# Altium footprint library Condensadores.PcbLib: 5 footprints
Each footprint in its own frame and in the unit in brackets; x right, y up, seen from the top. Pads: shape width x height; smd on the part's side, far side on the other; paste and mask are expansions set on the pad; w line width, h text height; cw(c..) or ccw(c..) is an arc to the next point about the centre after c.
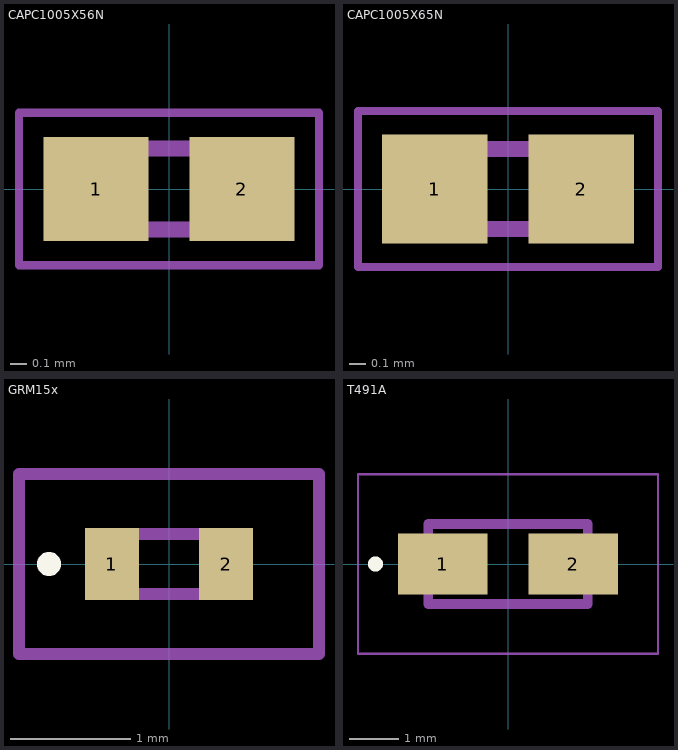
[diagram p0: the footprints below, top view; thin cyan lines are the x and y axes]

## CAPC1005X56N [mm]
pads (2):
  rect 0.65x0.64 smd: 1(-0.45,0) 2(0.45,0)
Mechanical 13:
  lines w0.1: -0.5,-0.25 0.5,-0.25 0.5,0.25 -0.5,0.25 -0.5,-0.25
Mechanical 15:
  lines w0.05: -0.925,-0.47 0.925,-0.47 0.925,0.47 -0.925,0.47 -0.925,-0.47
3D body "0402YC104KAT2A.stp": height 0.56, standoff 0, extent -0.5,-0.25 0.5,0.25

## CAPC1005X65N [mm]
pads (2):
  rect 0.66x0.68 smd: 1(-0.46,0) 2(0.46,0)
Mechanical 13:
  lines w0.1: -0.5,-0.25 -0.5,0.25 0.5,0.25 0.5,-0.25 -0.5,-0.25
Mechanical 15:
  lines w0.05: -0.94,-0.49 -0.94,0.49 0.94,0.49 0.94,-0.49 -0.94,-0.49
3D body "CL05A105KL5NRNC.stp": height 0.65, standoff 0, extent -0.5,-0.25 0.5,0.25

## GRM15x [mm]
pads (2):
  rect 0.45x0.6 smd: 1(-0.475,0) 2(0.475,0)
Top Overlay:
  lines w0.1: -1,-0.05 ccw(c-1,0) -1,0.05 ccw(c-1,0) -1,-0.05
Mechanical 13:
  lines w0.1: -0.5,-0.25 -0.5,0.25 0.5,0.25 0.5,-0.25 -0.5,-0.25
Mechanical 15:
  lines w0.1: -1.25,-0.75 -1.25,0.75 1.25,0.75 1.25,-0.75 -1.25,-0.75
3D body "GRM155R61A106ME11J.stp": height 0.5, standoff 0, extent -0.5,-0.28 0.5,0.27

## PCBComponent_1 [mm]

## T491A [mm]
pads (2):
  rect 1.8x1.23 smd: 1(-1.31,0) 2(1.31,0)
Top Overlay:
  circle w0.2: c-2.66,0 r0.05
Mechanical 13:
  lines w0.2: -1.6,-0.8 -1.6,0.8 1.6,0.8 1.6,-0.8 -1.6,-0.8
Mechanical 15:
  lines w0.05: -3.01,-1.8 -3.01,1.8 3.01,1.8 3.01,-1.8 -3.01,-1.8
3D body "T491A106K020AT.stp": height 1.81, standoff 0, extent -1.7,-0.9 1.7,0.9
